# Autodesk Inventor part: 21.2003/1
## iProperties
Created: 2007-05
Part Number: 21.2003/1
Document SubType Name: Modeling
Designer: Andy Moles
Material: UHMW, Black
Mass: 5.14406 g
Surface Area: 23.5238 cm^2
Volume: 5.4724 cm^3
Density: 0.94 g/cm^3
Description: L = .787" MACHINE TO 21.2003/1
Stock Number: 22.1088 SLIDE BAR 8
Vendor: F
Author: Andy Moles
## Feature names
1. Extrusion1
